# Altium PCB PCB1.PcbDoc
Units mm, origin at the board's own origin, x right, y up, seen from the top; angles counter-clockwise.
Board outline 152.4 x 101.6 mm, 2 copper layers (Top Layer, Bottom Layer); 3 components, 0 nets, 204 pads, 0 vias.
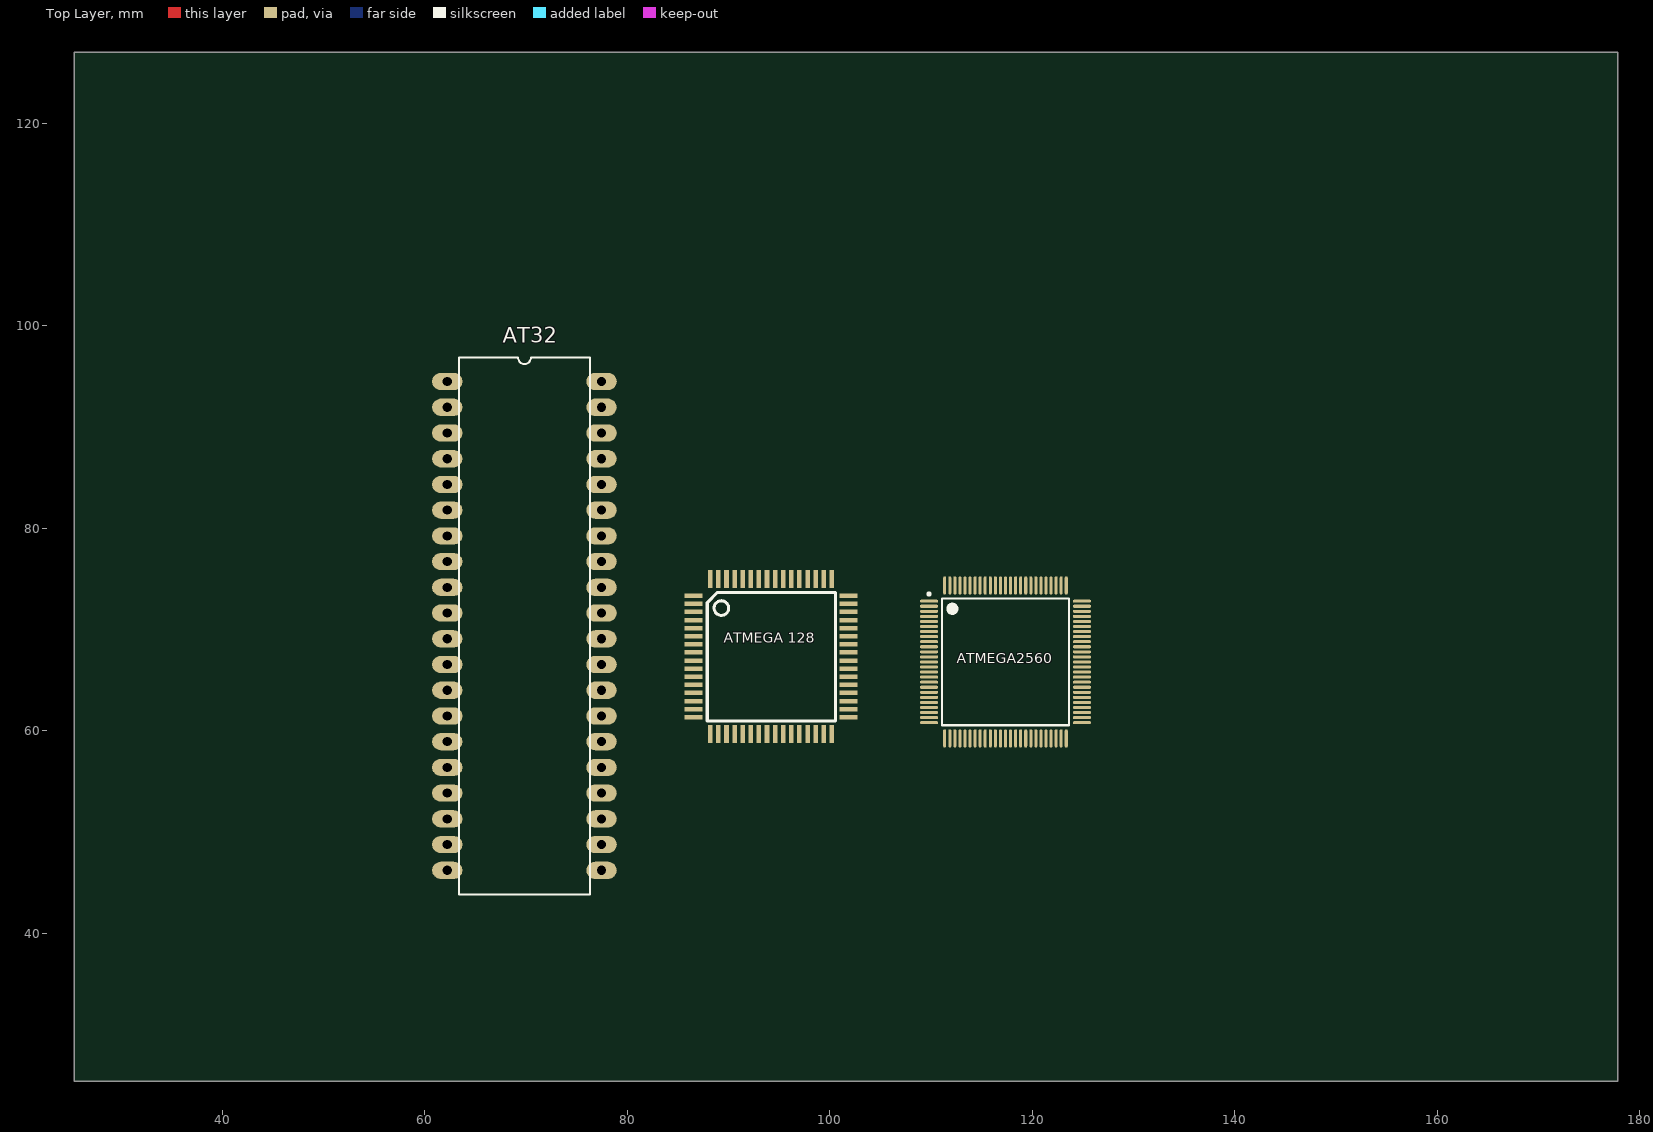
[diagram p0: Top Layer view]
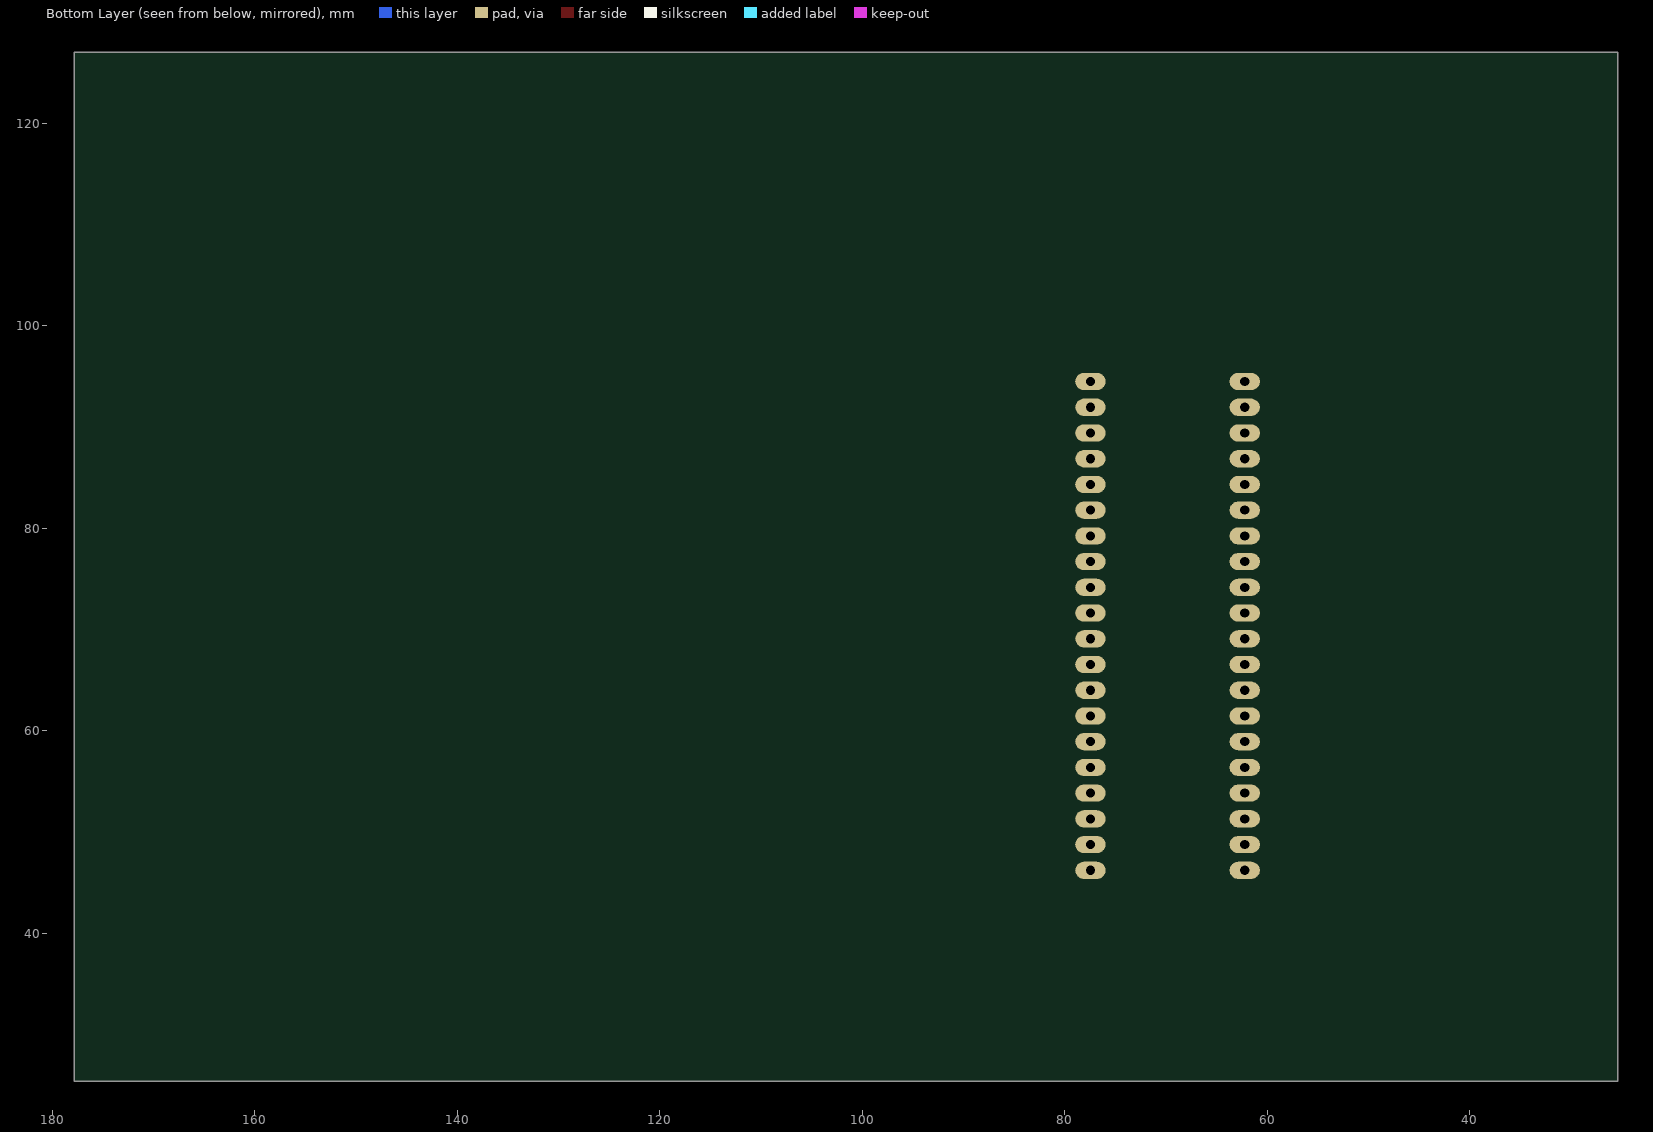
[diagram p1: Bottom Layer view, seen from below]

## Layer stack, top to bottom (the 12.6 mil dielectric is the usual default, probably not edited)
Top Solder: solder mask 0.0102, Solder Resist, Dk 3.5
Top Layer: signal copper 0.0356
Dielectric 1: dielectric 0.32, FR-4, Dk 4.8
Bottom Layer: signal copper 0.0356
Bottom Solder: solder mask 0.0102, Solder Resist, Dk 3.5

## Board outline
25.4,25.4 177.8,25.4 177.8,127 25.4,127

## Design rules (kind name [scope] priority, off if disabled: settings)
Clearance [All] p1: gap=0.254 ignorepadtopadclearanceinfootprint=FALSE except(0: Arc-Hole Track-Hole SMDPad-Hole THPad-Hole Via-Hole Fill-Hole Poly-Hole Region-Hole Text-Hole)
PolygonConnect [All] p1: connectstyle=Relief reliefconductorwidth=0.254 reliefentries=4 polygonreliefangle="90 Angle" airgapwidth=0.254
RoutingVias [All] p1: holewidth=0.711 width=1.27 viastyle="Through Hole" minholewidth=0.711 minwidth=1.27 maxholewidth=0.711 maxwidth=1.27
SolderMaskExpansion [All] p1: expansion=0.102
Width [All] p1: maxlimit=0.254 minlimit=0.254 preferedwidth=0.254
30 further rules are at their usual default settings.

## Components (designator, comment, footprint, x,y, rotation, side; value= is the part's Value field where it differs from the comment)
AT32 "AT 32 arduino" Dip40 69.85,70.358 r270 top (schematic designator AT1)
ATMEGA2560 "ATMEGA 2560 MEGA CORE" "ATMEGA 2560" 117.348,66.802 r0 top (schematic designator ATMEGA1)
"ATMEGA 128" "ATMEGA 128 ARDUINO" "ATMEGA 128 64 ARDUINO" 86.552,73.34 r0 top (schematic designator "ATMEGA 1")

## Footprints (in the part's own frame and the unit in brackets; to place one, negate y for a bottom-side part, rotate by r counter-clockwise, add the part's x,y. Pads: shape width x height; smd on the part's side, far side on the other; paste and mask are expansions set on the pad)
"ATMEGA 128 64 ARDUINO" [mm]
  rect 1.8x0.45 smd: 0(0,-0.8) 1(0,-1.6) 3(0,-3.2) 4(0,-4) 5(0,-4.8) 6(0,-5.6) 7(0,-6.4) 8(0,-7.2) 9(0,-8) 10(0,-8.8) 11(0,-9.6) 12(0,-10.4) 13(0,-11.2) 14(0,-12) 26(15.3,-12) 27(15.3,-11.2) 28(15.3,-10.4) 29(15.3,-9.6) 30(15.3,-8.8) 31(15.3,-8) 32(15.3,-7.2) 33(15.3,-6.4) 34(15.3,-5.6) 35(15.3,-4.8) 36(15.3,-4) 37(15.3,-3.2) 38(15.3,-2.4) 39(15.3,-1.6) 40(15.3,-0.8) 41(15.3,0) 53(0,0)
  rect 1.75x0.45 smd: 2(0,-2.4)
  rect 0.45x1.8 smd: 15(1.65,-13.65) 16(2.45,-13.65) 17(3.25,-13.65) 18(8.05,-13.65) 19(8.85,-13.65) 20(9.65,-13.65) 21(10.45,-13.65) 22(11.25,-13.65) 23(12.05,-13.65) 24(12.85,-13.65) 25(13.65,-13.65) 42(13.65,1.65) 43(12.85,1.65) 44(12.05,1.65) 45(4.05,1.65) 46(4.85,1.65) 47(5.65,1.65) 48(6.45,1.65) 49(7.25,1.65) 50(8.05,1.65) 51(8.85,1.65) 52(9.65,1.65) AREF(3.25,1.65) GND(2.45,1.65) GND(5.65,-13.65) GND(10.45,1.65) RST(4.05,-13.65) VCC(4.85,-13.65) VCC(11.25,1.65) X1(7.25,-13.65) X2(6.45,-13.65)
  rect 0.45x1.75 smd: AVCC(1.65,1.65)
  silkscreen extent 1.35,-12.37 14.02,0.33
"ATMEGA 2560" [mm] "Thin QFP, 100-Leads, Body 14x14mm, Pitch 0.5mm, IPC Medium Density"
  oval 1.8x0.3 smd: 1(-7.55,6) 2(-7.55,5.5) 3(-7.55,5) 4(-7.55,4.5) 5(-7.55,4) 6(-7.55,3.5) 7(-7.55,3) 8(-7.55,2.5) 9(-7.55,2) 10(-7.55,1.5) 11(-7.55,1) 12(-7.55,0.5) 13(-7.55,0) 14(-7.55,-0.5) 15(-7.55,-1) 16(-7.55,-1.5) 17(-7.55,-2) 18(-7.55,-2.5) 19(-7.55,-3) 20(-7.55,-3.5) 21(-7.55,-4) 22(-7.55,-4.5) 23(-7.55,-5) 24(-7.55,-5.5) 25(-7.55,-6) 51(7.55,-6) 52(7.55,-5.5) 53(7.55,-5) 54(7.55,-4.5) 55(7.55,-4) 56(7.55,-3.5) 57(7.55,-3) 58(7.55,-2.5) 59(7.55,-2) 60(7.55,-1.5) 61(7.55,-1) 62(7.55,-0.5) 63(7.55,0) 64(7.55,0.5) 65(7.55,1) 66(7.55,1.5) 67(7.55,2) 68(7.55,2.5) 69(7.55,3) 70(7.55,3.5) 71(7.55,4) 72(7.55,4.5) 73(7.55,5) 74(7.55,5.5) 75(7.55,6)
  oval 0.3x1.8 smd: 26(-6,-7.55) 27(-5.5,-7.55) 28(-5,-7.55) 29(-4.5,-7.55) 30(-4,-7.55) 31(-3.5,-7.55) 32(-3,-7.55) 33(-2.5,-7.55) 34(-2,-7.55) 35(-1.5,-7.55) 36(-1,-7.55) 37(-0.5,-7.55) 38(0,-7.55) 39(0.5,-7.55) 40(1,-7.55) 41(1.5,-7.55) 42(2,-7.55) 43(2.5,-7.55) 44(3,-7.55) 45(3.5,-7.55) 46(4,-7.55) 47(4.5,-7.55) 48(5,-7.55) 49(5.5,-7.55) 50(6,-7.55) 76(6,7.55) 77(5.5,7.55) 78(5,7.55) 79(4.5,7.55) 80(4,7.55) 81(3.5,7.55) 82(3,7.55) 83(2.5,7.55) 84(2,7.55) 85(1.5,7.55) 86(1,7.55) 87(0.5,7.55) 88(0,7.55) 89(-0.5,7.55) 90(-1,7.55) 91(-1.5,7.55) 92(-2,7.55) 93(-2.5,7.55) 94(-3,7.55) 95(-3.5,7.55) 96(-4,7.55) 97(-4.5,7.55) 98(-5,7.55) 99(-5.5,7.55) 100(-6,7.55)
  silkscreen extent -7.67,-6.25 6.25,6.82, body extent -7,-7 7,7, height 1.2
Dip40 [mm]
  oval 1.7x3 hole 0.9: 0(-24.13,-7.62) 1(-21.59,-7.62) 2(-19.05,-7.62) 3(-16.51,-7.62) 4(-13.97,-7.62) 5(-11.43,-7.62) 6(-8.89,-7.62) 7(-6.35,-7.62) 8(8.89,-7.62) 9(11.43,-7.62) 10(13.97,-7.62) 11(16.51,-7.62) 12(19.05,-7.62) 13(21.59,-7.62) 14(24.13,-7.62) 15(24.13,7.62) 16(21.59,7.62) 17(19.05,7.62) 18(16.51,7.62) 19(13.97,7.62) 20(11.43,7.62) 21(8.89,7.62) 22(6.35,7.62) 23(3.81,7.62) 24(-24.13,7.62) 25(-21.59,7.62) 26(-19.05,7.62) 27(-16.51,7.62) 28(-13.97,7.62) 29(-11.43,7.62) 30(-8.89,7.62) 31(-6.35,7.62) AREF(-3.81,7.62) AVCC(1.27,7.62) GND(-1.27,7.62) GND(1.27,-7.62) RST(-3.81,-7.62) VCC(-1.27,-7.62) X1(6.35,-7.62) X2(3.81,-7.62)
  silkscreen extent -26.5,-6.45 26.5,6.45

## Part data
AT32: library part "ATMEGA 32 ARDUINO"
ATMEGA2560: library part "ATMEGA 2560 ARDUINO MEGA PIN OUT"

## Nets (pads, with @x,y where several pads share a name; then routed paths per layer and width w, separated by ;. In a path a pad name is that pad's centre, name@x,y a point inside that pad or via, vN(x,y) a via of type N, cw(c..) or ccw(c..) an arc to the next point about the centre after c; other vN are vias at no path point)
pads on no net: "ATMEGA 128.0" "ATMEGA 128.1" "ATMEGA 128.2" "ATMEGA 128.3" "ATMEGA 128.4" "ATMEGA 128.5" "ATMEGA 128.6" "ATMEGA 128.7" "ATMEGA 128.8" "ATMEGA 128.9" "ATMEGA 128.10" "ATMEGA 128.11" "ATMEGA 128.12" "ATMEGA 128.13" "ATMEGA 128.14" "ATMEGA 128.15" "ATMEGA 128.16" "ATMEGA 128.17" "ATMEGA 128.18" "ATMEGA 128.19" "ATMEGA 128.20" "ATMEGA 128.21" "ATMEGA 128.22" "ATMEGA 128.23" "ATMEGA 128.24" "ATMEGA 128.25" "ATMEGA 128.26" "ATMEGA 128.27" "ATMEGA 128.28" "ATMEGA 128.29" "ATMEGA 128.30" "ATMEGA 128.31" "ATMEGA 128.32" "ATMEGA 128.33" "ATMEGA 128.34" "ATMEGA 128.35" "ATMEGA 128.36" "ATMEGA 128.37" "ATMEGA 128.38" "ATMEGA 128.39" "ATMEGA 128.40" "ATMEGA 128.41" "ATMEGA 128.42" "ATMEGA 128.43" "ATMEGA 128.44" "ATMEGA 128.45" "ATMEGA 128.46" "ATMEGA 128.47" "ATMEGA 128.48" "ATMEGA 128.49" "ATMEGA 128.50" "ATMEGA 128.51" "ATMEGA 128.52" "ATMEGA 128.53" "ATMEGA 128.AREF" "ATMEGA 128.AVCC" "ATMEGA 128.GND" "ATMEGA 128.RST" "ATMEGA 128.VCC" "ATMEGA 128.X1" "ATMEGA 128.X2" AT32.0 AT32.1 AT32.2 AT32.3 AT32.4 AT32.5 AT32.6 AT32.7 AT32.8 AT32.9 AT32.10 AT32.11 AT32.12 AT32.13 AT32.14 AT32.15 AT32.16 AT32.17 AT32.18 AT32.19 AT32.20 AT32.21 AT32.22 AT32.23 AT32.24 AT32.25 AT32.26 AT32.27 AT32.28 AT32.29 AT32.30 AT32.31 AT32.AREF AT32.AVCC AT32.GND AT32.RST AT32.VCC AT32.X1 AT32.X2 ATMEGA2560.1 ATMEGA2560.2 ATMEGA2560.3 ATMEGA2560.4 ATMEGA2560.5 ATMEGA2560.6 ATMEGA2560.7 ATMEGA2560.8 ATMEGA2560.9 ATMEGA2560.10 ATMEGA2560.11 ATMEGA2560.12 ATMEGA2560.13 ATMEGA2560.14 ATMEGA2560.15 ATMEGA2560.16 ATMEGA2560.17 ATMEGA2560.18 ATMEGA2560.19 ATMEGA2560.20 ATMEGA2560.21 ATMEGA2560.22 ATMEGA2560.23 ATMEGA2560.24 ATMEGA2560.25 ATMEGA2560.26 ATMEGA2560.27 ATMEGA2560.28 ATMEGA2560.29 ATMEGA2560.30 ATMEGA2560.31 ATMEGA2560.32 ATMEGA2560.33 ATMEGA2560.34 ATMEGA2560.35 ATMEGA2560.36 ATMEGA2560.37 ATMEGA2560.38 ATMEGA2560.39 ATMEGA2560.40 ATMEGA2560.41 ATMEGA2560.42 ATMEGA2560.43 ATMEGA2560.44 ATMEGA2560.45 ATMEGA2560.46 ATMEGA2560.47 ATMEGA2560.48 ATMEGA2560.49 ATMEGA2560.50 ATMEGA2560.51 ATMEGA2560.52 ATMEGA2560.53 ATMEGA2560.54 ATMEGA2560.55 ATMEGA2560.56 ATMEGA2560.57 ATMEGA2560.58 ATMEGA2560.59 ATMEGA2560.60 ATMEGA2560.61 ATMEGA2560.62 ATMEGA2560.63 ATMEGA2560.64 ATMEGA2560.65 ATMEGA2560.66 ATMEGA2560.67 ATMEGA2560.68 ATMEGA2560.69 ATMEGA2560.70 ATMEGA2560.71 ATMEGA2560.72 ATMEGA2560.73 ATMEGA2560.74 ATMEGA2560.75 ATMEGA2560.76 ATMEGA2560.77 ATMEGA2560.78 ATMEGA2560.79 ATMEGA2560.80 ATMEGA2560.81 ATMEGA2560.82 ATMEGA2560.83 ATMEGA2560.84 ATMEGA2560.85 ATMEGA2560.86 ATMEGA2560.87 ATMEGA2560.88 ATMEGA2560.89 ATMEGA2560.90 ATMEGA2560.91 ATMEGA2560.92 ATMEGA2560.93 ATMEGA2560.94 ATMEGA2560.95 ATMEGA2560.96 ATMEGA2560.97 ATMEGA2560.98 ATMEGA2560.99 ATMEGA2560.100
